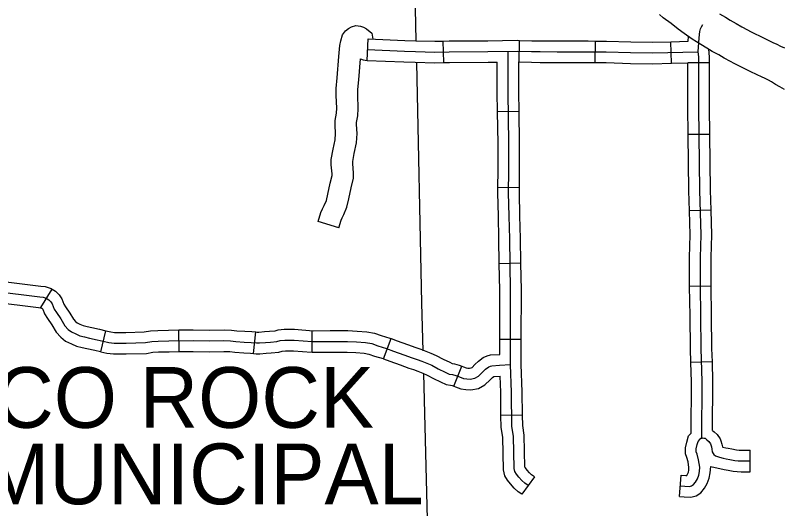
# Model space of a CAD drawing. Extents: x 1377389 to 1380723, y 1168351 to 1170484.
# Drawn here: x 1378616.9 to 1378723.7, y 1169324.4 to 1169393 of the extents above; entities that cross this region are included whole.
import ezdxf

# ---------------------------------------------------------------- set-up
doc = ezdxf.new("R2010")
doc.units = 0
doc.layers.add('B_Fill', color=7, linetype='Continuous')

msp = doc.modelspace()

# ---------------------------------------------------------------- linework, layer by layer
at = {"layer": 'B_Fill'}
for p, q in [((1378665.86, 1169386.74), (1378665.99, 1169389.74)), ((1378676.51, 1169386.43), (1378676.44, 1169389.42)), ((1378686.99, 1169386.52), (1378687.08, 1169389.52)), ((1378697.58, 1169386.44), (1378697.61, 1169389.43)), ((1378708.19, 1169386.34), (1378708.11, 1169389.34)), ((1378713.49, 1169386.39), (1378710.49, 1169386.39)), ((1378687, 1169379.62), (1378684, 1169379.58)), ((1378713.54, 1169376.45), (1378710.54, 1169376.41)), ((1378687.05, 1169369.02), (1378684.05, 1169369.06)), ((1378713.72, 1169365.92), (1378710.72, 1169365.83)), ((1378687.25, 1169358.51), (1378684.25, 1169358.46)), ((1378620.44, 1169352.36), (1378622.03, 1169354.91)), ((1378713.73, 1169355.34), (1378710.73, 1169355.3)), ((1378628.79, 1169346.22), (1378629.52, 1169349.13)), ((1378639.69, 1169346.24), (1378639.66, 1169349.24)), ((1378650.06, 1169345.98), (1378650.38, 1169348.96)), ((1378658.23, 1169346.14), (1378658.23, 1169349.14)), ((1378668.13, 1169345.23), (1378669.19, 1169348.04)), ((1378687.31, 1169347.92), (1378684.31, 1169347.92)), ((1378713.89, 1169344.81), (1378710.89, 1169344.71)), ((1378677.9, 1169341.43), (1378679.04, 1169344.2)), ((1378687.48, 1169337.38), (1378684.48, 1169337.34)), ((1378719.14, 1169329.52), (1378719.14, 1169332.52)), ((1378689.14, 1169328.82), (1378687.39, 1169326.38)), ((1378709.3, 1169326.07), (1378709.56, 1169329.06))]:
    msp.add_line(p, q, dxfattribs=at)
for points in [[(1378672.08, 1169416.42), (1378672.65, 1169389.47)], [(1378723.93, 1169382.67), (1378723.29, 1169383.04), (1378722.7, 1169383.4), (1378722.11, 1169383.76), (1378721.7, 1169383.98), (1378721.22, 1169384.21), (1378720.72, 1169384.45), (1378720.12, 1169384.72), (1378719.17, 1169385.2), (1378718.34, 1169385.63), (1378717.59, 1169385.99), (1378716.94, 1169386.3), (1378716.41, 1169386.58), (1378715.54, 1169387.06), (1378714.77, 1169387.5), (1378713.88, 1169387.99), (1378713.13, 1169388.45), (1378712.3, 1169388.93), (1378711.07, 1169389.71), (1378709.99, 1169390.47), (1378709.14, 1169391.09), (1378708.14, 1169391.87), (1378707.06, 1169392.66), (1378706.56, 1169393.1)], [(1378714.9, 1169393.2), (1378715.7, 1169392.74), (1378716.39, 1169392.32), (1378717.21, 1169391.86), (1378717.99, 1169391.42), (1378718.77, 1169390.99), (1378719.19, 1169390.77), (1378719.76, 1169390.49), (1378720.56, 1169390.11), (1378721.45, 1169389.66), (1378722.29, 1169389.23), (1378722.85, 1169388.97), (1378723.37, 1169388.72), (1378723.94, 1169388.46)], [(1378661.91, 1169363.43), (1378659.05, 1169364.34), (1378659.43, 1169365.56), (1378659.66, 1169366.09), (1378659.9, 1169366.57), (1378660.19, 1169367.25), (1378660.4, 1169368.13), (1378660.7, 1169369.65), (1378660.97, 1169370.71), (1378660.97, 1169370.94), (1378660.85, 1169372.2), (1378660.85, 1169372.96), (1378661.12, 1169374.38), (1378661.4, 1169375.67), (1378661.45, 1169376.56), (1378661.39, 1169377.73), (1378661.39, 1169378.39), (1378661.58, 1169379.41), (1378661.63, 1169380.09), (1378661.57, 1169381.84), (1378661.57, 1169382.84), (1378661.7, 1169384.29), (1378661.94, 1169387.3), (1378662.07, 1169388.8), (1378662.21, 1169389.45), (1378662.42, 1169390.27), (1378662.87, 1169390.84), (1378663.27, 1169391.15), (1378663.7, 1169391.39), (1378664.29, 1169391.57), (1378664.93, 1169391.51), (1378665.34, 1169391.36), (1378665.76, 1169391.14), (1378666.49, 1169390.52), (1378666.65, 1169389.71)], [(1378712.43, 1169334.2), (1378712.48, 1169342.06), (1378712.33, 1169346.65), (1378712.29, 1169351.22), (1378712.23, 1169355.36), (1378712.23, 1169359.32), (1378712.33, 1169362.47), (1378712.14, 1169368.64), (1378711.99, 1169380.17), (1378711.99, 1169387.19), (1378711.93, 1169387.95), (1378712.05, 1169389.82), (1378712.08, 1169390.34), (1378712.14, 1169390.74), (1378712.26, 1169391.14), (1378712.39, 1169391.42), (1378712.55, 1169391.74)], [(1378665.99, 1169389.74), (1378671.09, 1169389.52), (1378672.63, 1169389.47), (1378675.29, 1169389.4), (1378676.44, 1169389.42)], [(1378676.44, 1169389.42), (1378677.26, 1169389.44), (1378682.66, 1169389.47), (1378686.73, 1169389.53), (1378687.08, 1169389.52)], [(1378687.08, 1169389.52), (1378688.78, 1169389.47), (1378689.96, 1169389.46), (1378692.32, 1169389.44), (1378696.6, 1169389.44), (1378697.61, 1169389.43)], [(1378697.61, 1169389.43), (1378699.16, 1169389.42), (1378702.56, 1169389.32), (1378705.54, 1169389.27), (1378708.11, 1169389.34)], [(1378708.11, 1169389.34), (1378710.52, 1169389.39)], [(1378710.52, 1169389.39), (1378710.56, 1169390.07)], [(1378665.92, 1169388.24), (1378671.04, 1169388.02), (1378672.59, 1169387.97), (1378675.29, 1169387.9), (1378677.28, 1169387.94), (1378682.67, 1169387.97), (1378686.72, 1169388.03), (1378688.75, 1169387.97), (1378689.95, 1169387.96), (1378692.31, 1169387.94), (1378696.59, 1169387.94), (1378699.13, 1169387.92), (1378702.52, 1169387.82), (1378705.55, 1169387.77), (1378711.93, 1169387.93)], [(1378688.26, 1169327.6), (1378687.82, 1169327.92), (1378687.37, 1169328.3), (1378686.96, 1169328.78), (1378686.64, 1169329.19), (1378686.42, 1169329.54), (1378686.32, 1169329.99), (1378686.22, 1169334.49), (1378686, 1169335.83), (1378685.94, 1169340.61), (1378685.81, 1169344.41), (1378685.81, 1169347.57), (1378685.82, 1169354.77), (1378685.7, 1169361.93), (1378685.62, 1169365.09), (1378685.55, 1169368.32), (1378685.58, 1169371.43), (1378685.57, 1169375.2), (1378685.46, 1169382.31), (1378685.46, 1169388.01)], [(1378713.49, 1169386.99), (1378713.49, 1169387.25), (1378713.41, 1169388.28)], [(1378661.91, 1169363.43), (1378662.25, 1169364.51), (1378662.38, 1169364.82), (1378662.62, 1169365.31), (1378663.05, 1169366.31), (1378663.33, 1169367.49), (1378663.63, 1169368.99), (1378663.97, 1169370.34), (1378663.97, 1169371.08), (1378663.85, 1169372.35), (1378663.85, 1169372.68), (1378664.06, 1169373.78), (1378664.38, 1169375.27), (1378664.45, 1169376.55), (1378664.39, 1169377.8), (1378664.39, 1169378.11), (1378664.56, 1169379.02), (1378664.63, 1169380.03), (1378664.57, 1169381.89), (1378664.57, 1169382.71), (1378664.69, 1169384.04), (1378664.92, 1169386.95), (1378665.31, 1169386.83), (1378665.86, 1169386.73)], [(1378713.54, 1169376.45), (1378713.49, 1169380.18), (1378713.49, 1169386.99)], [(1378665.86, 1169386.74), (1378670.98, 1169386.52), (1378672.54, 1169386.47), (1378675.29, 1169386.39), (1378676.51, 1169386.43)], [(1378672.71, 1169386.46), (1378673.42, 1169352.98), (1378673.59, 1169346.34)], [(1378676.51, 1169386.43), (1378677.31, 1169386.44), (1378682.69, 1169386.47), (1378683.96, 1169386.49)], [(1378684, 1169379.58), (1378683.96, 1169382.29), (1378683.96, 1169386.49)], [(1378687, 1169379.62), (1378686.96, 1169382.32), (1378686.96, 1169386.52)], [(1378686.96, 1169386.52), (1378688.71, 1169386.47), (1378689.94, 1169386.46), (1378692.31, 1169386.44), (1378696.59, 1169386.44), (1378697.58, 1169386.44)], [(1378697.58, 1169386.44), (1378699.1, 1169386.42), (1378702.49, 1169386.32), (1378705.55, 1169386.27), (1378708.19, 1169386.34)], [(1378708.19, 1169386.34), (1378710.49, 1169386.39)], [(1378710.54, 1169376.41), (1378710.49, 1169380.16), (1378710.49, 1169386.39)], [(1378684.05, 1169369.06), (1378684.08, 1169371.44), (1378684.07, 1169375.18), (1378684, 1169379.58)], [(1378687.05, 1169369.02), (1378687.08, 1169371.43), (1378687.07, 1169375.21), (1378687, 1169379.62)], [(1378710.72, 1169365.83), (1378710.64, 1169368.61), (1378710.54, 1169376.41)], [(1378713.72, 1169365.92), (1378713.64, 1169368.67), (1378713.54, 1169376.45)], [(1378684.25, 1169358.46), (1378684.2, 1169361.9), (1378684.12, 1169365.05), (1378684.04, 1169368.31), (1378684.05, 1169369.06)], [(1378687.25, 1169358.51), (1378687.2, 1169361.96), (1378687.12, 1169365.13), (1378687.05, 1169368.32), (1378687.05, 1169369.02)], [(1378710.73, 1169355.3), (1378710.73, 1169355.35), (1378710.73, 1169359.34), (1378710.82, 1169362.47), (1378710.72, 1169365.83)], [(1378713.73, 1169355.34), (1378713.73, 1169355.37), (1378713.73, 1169359.3), (1378713.83, 1169362.48), (1378713.72, 1169365.92)], [(1378684.31, 1169347.92), (1378684.32, 1169354.76), (1378684.25, 1169358.46)], [(1378687.31, 1169347.92), (1378687.32, 1169354.78), (1378687.25, 1169358.51)], [(1378610.88, 1169356.55), (1378611.37, 1169356.52), (1378611.97, 1169356.52), (1378612.54, 1169356.42), (1378612.92, 1169356.29), (1378613.06, 1169356.25), (1378613.31, 1169356.22), (1378614.09, 1169356.14), (1378620.46, 1169355.35), (1378621.08, 1169355.29), (1378621.88, 1169355), (1378622.03, 1169354.91)], [(1378622.03, 1169354.91), (1378622.49, 1169354.62), (1378622.99, 1169354.12), (1378623.38, 1169353.58), (1378623.67, 1169352.81), (1378623.88, 1169352.48), (1378624.5, 1169351.6), (1378625.01, 1169350.73), (1378625.3, 1169350.41), (1378625.52, 1169350.24), (1378625.9, 1169350.06), (1378626.37, 1169349.87), (1378626.89, 1169349.74), (1378627.55, 1169349.58), (1378628.63, 1169349.34), (1378629.48, 1169349.14), (1378629.52, 1169349.13)], [(1378710.89, 1169344.71), (1378710.83, 1169346.62), (1378710.79, 1169351.21), (1378710.73, 1169355.3)], [(1378713.89, 1169344.81), (1378713.82, 1169346.68), (1378713.79, 1169351.24), (1378713.73, 1169355.34)], [(1378613.92, 1169354.65), (1378620.3, 1169353.86), (1378620.76, 1169353.81), (1378621.21, 1169353.65), (1378621.55, 1169353.44), (1378621.84, 1169353.15), (1378622.05, 1169352.86), (1378622.32, 1169352.14), (1378622.63, 1169351.65), (1378623.24, 1169350.79), (1378623.8, 1169349.83), (1378624.27, 1169349.32), (1378624.71, 1169348.96), (1378625.31, 1169348.68), (1378625.9, 1169348.44), (1378626.54, 1169348.28), (1378627.22, 1169348.12), (1378628.29, 1169347.88), (1378629.12, 1169347.68), (1378629.92, 1169347.48), (1378630.64, 1169347.41), (1378631.43, 1169347.41), (1378632.31, 1169347.41), (1378635.01, 1169347.48), (1378635.88, 1169347.64), (1378636.8, 1169347.68), (1378638.27, 1169347.72), (1378641.65, 1169347.76), (1378643.96, 1169347.72), (1378645.94, 1169347.76), (1378646.86, 1169347.72), (1378647.57, 1169347.64), (1378648.77, 1169347.56), (1378649.72, 1169347.52), (1378650.48, 1169347.44), (1378650.87, 1169347.44), (1378651.71, 1169347.52), (1378652.39, 1169347.56), (1378653.3, 1169347.64), (1378653.78, 1169347.76), (1378654.41, 1169347.84), (1378655.17, 1169347.84), (1378655.69, 1169347.84), (1378658.23, 1169347.64)], [(1378610.72, 1169353.55), (1378611.29, 1169353.52), (1378611.69, 1169353.52), (1378611.79, 1169353.51), (1378612.03, 1169353.42), (1378612.48, 1169353.3), (1378612.98, 1169353.24), (1378613.74, 1169353.16), (1378620.14, 1169352.36), (1378620.43, 1169352.34), (1378620.55, 1169352.29), (1378620.44, 1169352.36)], [(1378620.44, 1169352.36), (1378620.61, 1169352.26), (1378620.69, 1169352.17), (1378620.72, 1169352.14), (1378620.97, 1169351.48), (1378621.38, 1169350.82), (1378621.98, 1169349.97), (1378622.58, 1169348.94), (1378623.24, 1169348.22), (1378623.91, 1169347.68), (1378624.71, 1169347.3), (1378625.44, 1169347.01), (1378626.19, 1169346.82), (1378626.88, 1169346.66), (1378627.95, 1169346.42), (1378628.77, 1169346.23), (1378628.79, 1169346.22)], [(1378629.52, 1169349.13), (1378630.19, 1169348.96), (1378630.72, 1169348.91), (1378631.43, 1169348.91), (1378632.28, 1169348.91), (1378634.85, 1169348.98), (1378635.72, 1169349.14), (1378636.75, 1169349.18), (1378638.24, 1169349.22), (1378639.66, 1169349.24)], [(1378639.66, 1169349.24), (1378641.65, 1169349.26), (1378643.95, 1169349.22), (1378645.96, 1169349.26), (1378646.97, 1169349.22), (1378647.71, 1169349.14), (1378648.85, 1169349.06), (1378649.83, 1169349.02), (1378650.38, 1169348.96)], [(1378650.38, 1169348.96), (1378650.56, 1169348.94), (1378650.8, 1169348.94), (1378651.59, 1169349.02), (1378652.28, 1169349.06), (1378653.05, 1169349.13), (1378653.5, 1169349.24), (1378654.32, 1169349.34), (1378655.17, 1169349.34), (1378655.74, 1169349.34), (1378658.35, 1169349.14)], [(1378658.23, 1169349.14), (1378660.71, 1169349.15), (1378662.05, 1169349.15), (1378663.15, 1169349.15), (1378664.45, 1169349.08), (1378665.82, 1169348.98), (1378666.87, 1169348.8), (1378667.81, 1169348.46), (1378669.03, 1169348.09), (1378669.19, 1169348.04)], [(1378658.23, 1169347.64), (1378660.71, 1169347.65), (1378662.05, 1169347.65), (1378663.11, 1169347.65), (1378664.36, 1169347.59), (1378665.63, 1169347.49), (1378666.49, 1169347.34), (1378667.34, 1169347.04), (1378668.55, 1169346.67), (1378669.53, 1169346.31), (1378670.98, 1169345.79), (1378672.14, 1169345.36), (1378672.81, 1169345.15), (1378673.48, 1169344.88), (1378674.18, 1169344.6), (1378674.84, 1169344.33), (1378675.76, 1169343.84), (1378676.7, 1169343.39), (1378677.28, 1169343.11), (1378677.73, 1169343.05), (1378678.19, 1169342.93), (1378678.71, 1169342.72), (1378679.25, 1169342.5), (1378679.74, 1169342.44), (1378680.19, 1169342.41), (1378680.83, 1169342.54), (1378681.35, 1169342.81), (1378681.9, 1169343.36), (1378682.32, 1169343.78), (1378682.78, 1169344.12), (1378683.02, 1169344.22), (1378683.23, 1169344.27), (1378684.27, 1169344.33), (1378685.81, 1169344.45)], [(1378669.19, 1169348.04), (1378670.04, 1169347.72), (1378671.49, 1169347.2), (1378672.63, 1169346.78), (1378673.32, 1169346.56), (1378674.03, 1169346.27), (1378674.73, 1169346), (1378675.48, 1169345.69), (1378676.44, 1169345.18), (1378677.35, 1169344.74), (1378677.71, 1169344.57), (1378678.03, 1169344.53), (1378678.67, 1169344.35), (1378679.04, 1169344.2)], [(1378684.31, 1169345.84), (1378684.31, 1169347.57), (1378684.31, 1169347.92)], [(1378687.48, 1169337.38), (1378687.44, 1169340.65), (1378687.31, 1169344.43), (1378687.31, 1169347.57), (1378687.31, 1169347.92)], [(1378628.79, 1169346.22), (1378629.65, 1169346), (1378630.55, 1169345.91), (1378631.43, 1169345.91), (1378632.33, 1169345.91), (1378635.17, 1169345.99), (1378636.05, 1169346.15), (1378636.85, 1169346.18), (1378638.3, 1169346.22), (1378639.69, 1169346.24)], [(1378639.69, 1169346.24), (1378641.65, 1169346.26), (1378643.96, 1169346.22), (1378645.93, 1169346.26), (1378646.74, 1169346.23), (1378647.44, 1169346.15), (1378648.69, 1169346.07), (1378649.61, 1169346.03), (1378650.06, 1169345.98)], [(1378650.06, 1169345.98), (1378650.4, 1169345.94), (1378650.95, 1169345.94), (1378651.82, 1169346.03), (1378652.49, 1169346.07), (1378653.55, 1169346.16), (1378654.05, 1169346.29), (1378654.51, 1169346.34), (1378655.17, 1169346.34), (1378655.63, 1169346.34), (1378658.11, 1169346.15)], [(1378658.23, 1169346.14), (1378660.71, 1169346.15), (1378662.05, 1169346.15), (1378663.07, 1169346.15), (1378664.27, 1169346.09), (1378665.45, 1169346), (1378666.1, 1169345.89), (1378666.87, 1169345.61), (1378668.07, 1169345.25), (1378668.13, 1169345.23)], [(1378679.04, 1169344.2), (1378679.26, 1169344.11), (1378679.62, 1169343.97), (1378679.88, 1169343.94), (1378680.1, 1169343.92), (1378680.33, 1169343.97), (1378680.45, 1169344.03), (1378680.84, 1169344.42), (1378681.34, 1169344.92), (1378682.02, 1169345.42), (1378682.56, 1169345.66), (1378683.04, 1169345.76), (1378684.31, 1169345.84)], [(1378668.13, 1169345.23), (1378669.01, 1169344.9), (1378670.47, 1169344.38), (1378671.65, 1169343.95), (1378672.3, 1169343.74), (1378672.92, 1169343.49), (1378673.62, 1169343.21), (1378674.21, 1169342.97), (1378675.08, 1169342.51), (1378676.05, 1169342.03), (1378676.85, 1169341.66), (1378677.44, 1169341.58), (1378677.71, 1169341.51), (1378677.9, 1169341.43)], [(1378710.93, 1169334.89), (1378710.98, 1169342.04), (1378710.89, 1169344.71)], [(1378713.93, 1169335.26), (1378713.98, 1169342.08), (1378713.89, 1169344.81)], [(1378673.68, 1169343.19), (1378674.25, 1169321.07)], [(1378677.9, 1169341.43), (1378678.15, 1169341.33), (1378678.88, 1169341.04), (1378679.6, 1169340.95), (1378680.29, 1169340.9), (1378681.34, 1169341.1), (1378682.25, 1169341.59), (1378682.96, 1169342.3), (1378683.3, 1169342.64), (1378683.49, 1169342.78), (1378684.36, 1169342.83)], [(1378684.48, 1169337.34), (1378684.44, 1169340.58), (1378684.36, 1169342.83)], [(1378687.39, 1169326.38), (1378686.89, 1169326.73), (1378686.31, 1169327.23), (1378685.79, 1169327.83), (1378685.41, 1169328.33), (1378685.01, 1169328.96), (1378684.82, 1169329.81), (1378684.73, 1169334.35), (1378684.5, 1169335.69), (1378684.48, 1169337.34)], [(1378689.14, 1169328.82), (1378688.74, 1169329.1), (1378688.43, 1169329.36), (1378688.12, 1169329.73), (1378687.87, 1169330.05), (1378687.83, 1169330.12), (1378687.82, 1169330.16), (1378687.72, 1169334.63), (1378687.5, 1169335.96), (1378687.48, 1169337.38)], [(1378709.56, 1169329.06), (1378710.18, 1169329), (1378710.35, 1169329), (1378710.45, 1169329.17), (1378710.55, 1169329.44), (1378710.6, 1169329.74), (1378710.63, 1169330.11), (1378710.51, 1169330.88), (1378710.34, 1169331.51), (1378710.16, 1169332), (1378710.16, 1169332.83), (1378710.32, 1169333.65), (1378710.58, 1169334.5), (1378710.93, 1169334.89)], [(1378713.93, 1169335.26), (1378714.16, 1169335.07), (1378714.54, 1169334.69), (1378714.96, 1169334.11), (1378715.06, 1169333.81)], [(1378709.43, 1169327.56), (1378710.08, 1169327.51), (1378710.73, 1169327.48), (1378711.01, 1169327.56), (1378711.27, 1169327.73), (1378711.55, 1169328.07), (1378711.81, 1169328.53), (1378712, 1169329.04), (1378712.09, 1169329.55), (1378712.14, 1169330.17), (1378711.97, 1169331.19), (1378711.78, 1169331.95), (1378711.66, 1169332.27), (1378711.66, 1169332.69), (1378711.78, 1169333.29), (1378711.92, 1169333.74), (1378712.14, 1169334), (1378712.31, 1169334.17), (1378712.38, 1169334.19), (1378712.47, 1169334.21), (1378712.6, 1169334.22), (1378712.71, 1169334.21), (1378712.77, 1169334.2), (1378712.87, 1169334.17), (1378712.94, 1169334.14), (1378713.14, 1169333.97), (1378713.39, 1169333.71), (1378713.62, 1169333.4), (1378713.76, 1169333), (1378713.82, 1169332.64), (1378713.87, 1169332.27), (1378713.99, 1169332.04), (1378714.1, 1169331.9), (1378714.33, 1169331.73), (1378714.89, 1169331.53), (1378715.4, 1169331.39), (1378715.8, 1169331.3), (1378716.34, 1169331.22), (1378717.02, 1169331.1), (1378717.47, 1169331.05), (1378717.95, 1169331.02), (1378719.14, 1169331.02)], [(1378715.06, 1169333.81), (1378715.22, 1169333.37), (1378715.28, 1169332.98), (1378715.34, 1169332.96), (1378715.76, 1169332.85), (1378716.07, 1169332.78), (1378716.58, 1169332.7), (1378717.23, 1169332.59), (1378717.61, 1169332.54), (1378717.99, 1169332.52), (1378719.14, 1169332.52)], [(1378709.3, 1169326.07), (1378709.98, 1169326.01), (1378710.92, 1169325.97), (1378711.66, 1169326.19), (1378712.28, 1169326.61), (1378712.79, 1169327.22), (1378713.16, 1169327.88), (1378713.46, 1169328.64), (1378713.58, 1169329.35), (1378713.66, 1169330.23)], [(1378713.66, 1169330.23), (1378715.52, 1169329.83), (1378716.1, 1169329.74), (1378716.8, 1169329.62), (1378717.33, 1169329.55), (1378717.91, 1169329.52), (1378719.14, 1169329.52)]]:
    msp.add_lwpolyline(points, dxfattribs=at)

# ---------------------------------------------------------------- texts
for s, p in [('CALICO ROCK', (1378588.99, 1169335.63)), ('MUNICIPAL', (1378612.23, 1169325))]:
    msp.add_text(s, height=8.448, dxfattribs=at).set_placement(p)

doc.saveas('drawing.dxf')
